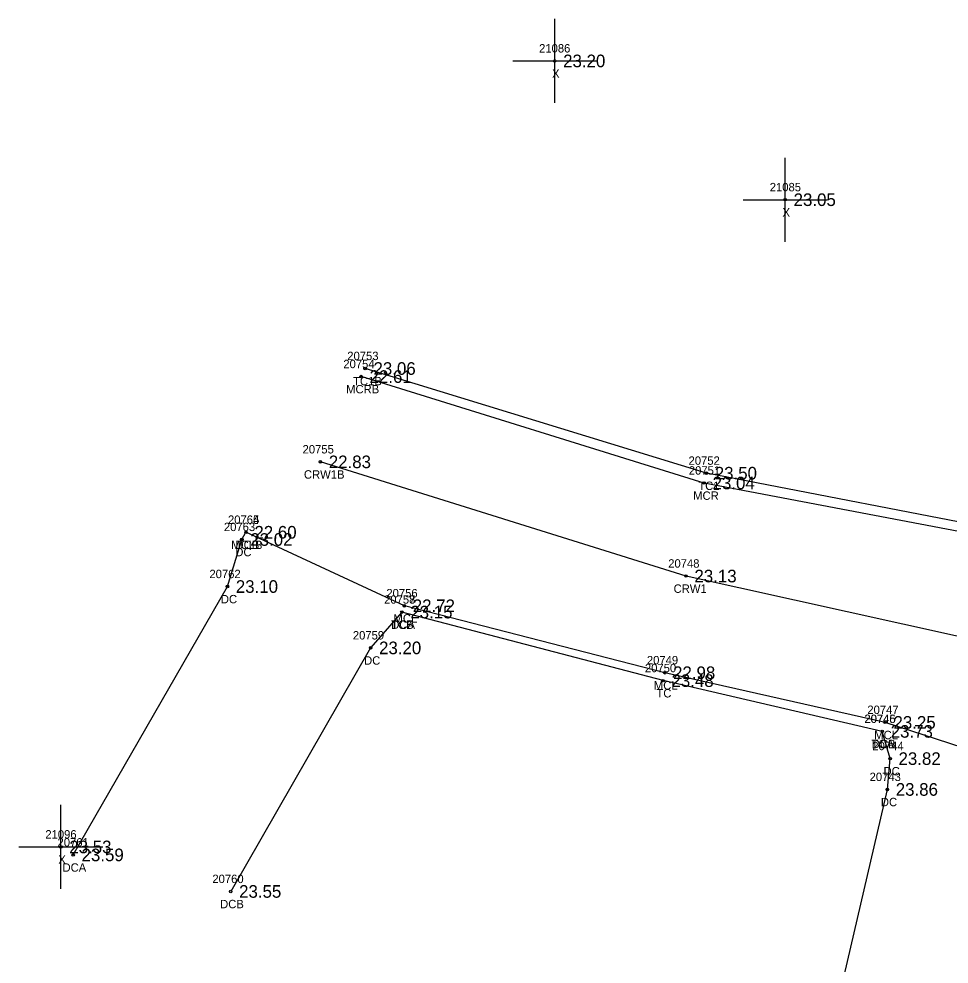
# Model space of a CAD drawing. Extents: x 2655177 to 2656219, y 761780 to 764748.
# Drawn here: x 2655261.1 to 2655371.8, y 762179.8 to 762292.3 of the extents above; entities that cross this region are included whole.
import ezdxf

# ---------------------------------------------------------------- set-up
doc = ezdxf.new("R2010")
doc.units = 0
for name, color, linetype in [('RD_DTM_BkLn1', 7, 'Continuous'), ('RD_DTM_BkLn2', 7, 'Continuous'), ('RD_EX_Conc', 7, 'Continuous'), ('RD_EX_Conc_txCode', 7, 'Continuous'), ('RD_EX_Misc', 7, 'Continuous'), ('RD_EX_Misc_txCode', 7, 'Continuous'), ('RD_EX_TX_Conc_ELEV', 7, 'Continuous'), ('RD_EX_TX_Misc_ELEV', 7, 'Continuous'), ('RD_HC_Survey_ELEV', 7, 'Continuous'), ('RD_HC_Survey_txCode', 7, 'Continuous'), ('RD_SMD_Locator', 7, 'Continuous')]:
    doc.layers.add(name, color=color, linetype=linetype)

msp = doc.modelspace()

# ---------------------------------------------------------------- linework, layer by layer
at = {"layer": 'RD_DTM_BkLn1'}
msp.add_lwpolyline([(2655412.23, 762209.57), (2655385.42, 762216.05), (2655340.47, 762226.03), (2655296.97, 762239.62)], dxfattribs=at)
at = {"layer": 'RD_DTM_BkLn2'}
for points in [[(2655380.21, 762231.07), (2655342.89, 762238.27), (2655302.29, 762250.73)], [(2655363.82, 762207.54), (2655337.74, 762213.58), (2655306.67, 762221.74)]]:
    msp.add_lwpolyline(points, dxfattribs=at)
at = {"layer": 'RD_EX_Conc'}
for points in [[(2655447.67, 762217.38), (2655447.33, 762216.45), (2655403.55, 762226.11), (2655380.02, 762230), (2655342.63, 762237.1), (2655301.82, 762249.77)], [(2655267.56, 762192.84), (2655285.91, 762224.78), (2655287.63, 762230.38), (2655288.12, 762231.24)], [(2655440.54, 762187.62), (2655439.06, 762188.62), (2655385.76, 762201.57), (2655364.15, 762208.61), (2655337.93, 762214.52), (2655306.96, 762222.49), (2655288.12, 762231.24)], [(2655306.67, 762221.74), (2655302.95, 762217.48), (2655286.3, 762188.49)], [(2655358.1, 762173.33), (2655364.42, 762200.63), (2655364.75, 762204.3), (2655363.82, 762207.54)]]:
    msp.add_lwpolyline(points, dxfattribs=at)
at = {"layer": 'RD_EX_Misc'}
for p, q in [((2655324.85, 762282.34), (2655324.85, 762292.34)), ((2655319.85, 762287.34), (2655329.85, 762287.34)), ((2655352.27, 762265.82), (2655352.27, 762275.82)), ((2655347.27, 762270.82), (2655357.27, 762270.82)), ((2655266.1, 762188.79), (2655266.1, 762198.79)), ((2655261.1, 762193.79), (2655271.1, 762193.79))]:
    msp.add_line(p, q, dxfattribs=at)
at = {"layer": 'RD_SMD_Locator'}
for centre in [(2655324.85, 762287.34), (2655352.27, 762270.82), (2655302.29, 762250.73), (2655301.82, 762249.77), (2655296.97, 762239.62), (2655342.89, 762238.27), (2655342.63, 762237.1), (2655287.63, 762230.38), (2655288.12, 762231.24), (2655288.12, 762231.24), (2655340.47, 762226.03), (2655285.91, 762224.78), (2655306.96, 762222.49), (2655306.67, 762221.74), (2655306.67, 762221.74), (2655302.95, 762217.48), (2655337.74, 762213.58), (2655337.93, 762214.52), (2655364.15, 762208.61), (2655363.82, 762207.54), (2655363.82, 762207.54), (2655364.75, 762204.3), (2655364.42, 762200.63), (2655266.1, 762193.79), (2655267.56, 762192.84), (2655286.3, 762188.49)]:
    msp.add_circle(centre, 0.15, dxfattribs=at)

# ---------------------------------------------------------------- texts
at = {"layer": 'RD_EX_Conc_txCode'}
for s, p in [('20753', (2655300.17, 762251.73)), ('20754', (2655299.7, 762250.77)), ('TC1B', (2655300.86, 762248.73)), ('MCRB', (2655300.03, 762247.77)), ('20752', (2655340.77, 762239.27)), ('20751', (2655340.8, 762238.1)), ('TC1', (2655341.93, 762236.27)), ('MCR', (2655341.32, 762235.1)), ('20764', (2655285.98, 762232.24)), ('20765', (2655285.98, 762232.24)), ('20763', (2655285.49, 762231.38)), ('MCLB', (2655286.36, 762229.24)), ('DC', (2655286.85, 762228.38)), ('DCB', (2655286.87, 762229.24)), ('20762', (2655283.77, 762225.78)), ('DC', (2655285.13, 762222.78)), ('20757', (2655304.55, 762222.74)), ('20758', (2655304.55, 762222.74)), ('20756', (2655304.82, 762223.49)), ('MCL', (2655305.67, 762220.49)), ('TCB', (2655305.4, 762219.74)), ('DCA', (2655305.4, 762219.74)), ('20759', (2655300.83, 762218.48)), ('DC', (2655302.17, 762215.48)), ('20749', (2655335.81, 762215.52)), ('20750', (2655335.58, 762214.58)), ('MCL', (2655336.64, 762212.52)), ('TC', (2655336.95, 762211.58)), ('20747', (2655362.04, 762209.61)), ('20746', (2655361.68, 762208.54)), ('20745', (2655361.7, 762208.54)), ('MCL', (2655362.86, 762206.61)), ('TCA', (2655362.54, 762205.54)), ('DCB', (2655362.57, 762205.54)), ('20744', (2655362.63, 762205.3)), ('20743', (2655362.31, 762201.63)), ('DC', (2655363.97, 762202.3)), ('DC', (2655363.65, 762198.63)), ('20761', (2655265.7, 762193.84)), ('DCA', (2655266.29, 762190.84)), ('20760', (2655284.12, 762189.49)), ('DCB', (2655285.04, 762186.49))]:
    msp.add_text(s, height=1, dxfattribs=at).set_placement(p)
at = {"layer": 'RD_EX_Misc_txCode'}
for s, p in [('21086', (2655322.99, 762288.34)), ('X', (2655324.53, 762285.34)), ('21085', (2655350.43, 762271.82)), ('X', (2655351.95, 762268.82)), ('21096', (2655264.25, 762194.79)), ('X', (2655265.79, 762191.79))]:
    msp.add_text(s, height=1, dxfattribs=at).set_placement(p)
at = {"layer": 'RD_EX_TX_Conc_ELEV'}
for s, p in [('23.06', (2655303.29, 762249.98)), ('22.61', (2655302.82, 762249.02)), ('23.50', (2655343.89, 762237.52)), ('23.04', (2655343.63, 762236.35)), ('22.60', (2655289.12, 762230.49)), ('22.60', (2655289.12, 762230.49)), ('23.02', (2655288.63, 762229.63)), ('23.10', (2655286.91, 762224.03)), ('22.72', (2655307.96, 762221.74)), ('23.15', (2655307.67, 762220.99)), ('23.15', (2655307.67, 762220.99)), ('23.20', (2655303.95, 762216.73)), ('22.98', (2655338.93, 762213.77)), ('23.48', (2655338.74, 762212.83)), ('23.25', (2655365.15, 762207.86)), ('23.73', (2655364.82, 762206.79)), ('23.73', (2655364.82, 762206.79)), ('23.82', (2655365.75, 762203.55)), ('23.86', (2655365.42, 762199.88)), ('23.59', (2655268.56, 762192.09)), ('23.55', (2655287.3, 762187.74))]:
    msp.add_text(s, height=1.5, dxfattribs=at).set_placement(p)
at = {"layer": 'RD_EX_TX_Misc_ELEV'}
for s, p in [('23.20', (2655325.85, 762286.59)), ('23.05', (2655353.27, 762270.07)), ('23.53', (2655267.1, 762193.04))]:
    msp.add_text(s, height=1.5, dxfattribs=at).set_placement(p)
at = {"layer": 'RD_HC_Survey_ELEV'}
for s, p in [('22.83', (2655297.97, 762238.87)), ('23.13', (2655341.47, 762225.28))]:
    msp.add_text(s, height=1.5, dxfattribs=at).set_placement(p)
at = {"layer": 'RD_HC_Survey_txCode'}
for s, p in [('20755', (2655294.85, 762240.62)), ('CRW1B', (2655295.01, 762237.62)), ('20748', (2655338.35, 762227.03)), ('CRW1', (2655338.99, 762224.03))]:
    msp.add_text(s, height=1, dxfattribs=at).set_placement(p)

doc.saveas('drawing.dxf')
